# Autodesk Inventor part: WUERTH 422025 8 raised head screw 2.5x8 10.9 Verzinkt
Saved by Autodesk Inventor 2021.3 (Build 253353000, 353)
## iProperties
Created: 2023-03
Part Number: WUERTH 422025 8 raised head screw 2.5x8 10.9 Verzinkt
Material: Generic
Document SubType Name: Modeling
Designer: AdminForWorker
Density: 1 g/cm^3
Appearance: Default
Title: WUERTH 422025 8 raised head screw 2.5x8 10.9 Verzinkt
Author: AdminForWorker
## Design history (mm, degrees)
feature "Body1"
body "Solid1"
